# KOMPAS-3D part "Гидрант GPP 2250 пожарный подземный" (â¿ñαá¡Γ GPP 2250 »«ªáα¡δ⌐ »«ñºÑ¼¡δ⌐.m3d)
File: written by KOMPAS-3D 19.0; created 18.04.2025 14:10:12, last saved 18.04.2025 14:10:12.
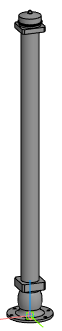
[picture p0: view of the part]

Document properties: Полное имя файла: E:\Dendor Работа Сачек\3D для проекитирвщиков\11.1 Тип GPP. Гидрант пожарный подземный\stp_Тип GPP. 750-6000 Гидрант пожарный подземный\Гидрант GPP 2250 пожарный подземный.m3d

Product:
- Part/product: Гидрант GPP 2250 пожарный подземный

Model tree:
1. Операция без истории:1  (labels: Гидрант GPP 2250 пожарный подземный)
